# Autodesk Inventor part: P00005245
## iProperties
Shininess: 64.0
Length Units: 11269
Angle Units: 11279
Time Units: 11290
Mass Units: 11283
Length Display Precision: 3
Angle Display Precision: 2
Compacted: True
Part Number: P00005245
Document SubType Name: Modeling
Created: 2004-01
Material: Standard
Designer: Mittelmeyer
Manufacturer: Standard
Standards Organization: Custom
Density: 0.0
Volumn: 0.0
Area: 0.0
PropertySet Name: Model Information
Control State: 0
Master: False
Checked Out: False
Author: Mittelmeyer
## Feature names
1. Basis1
